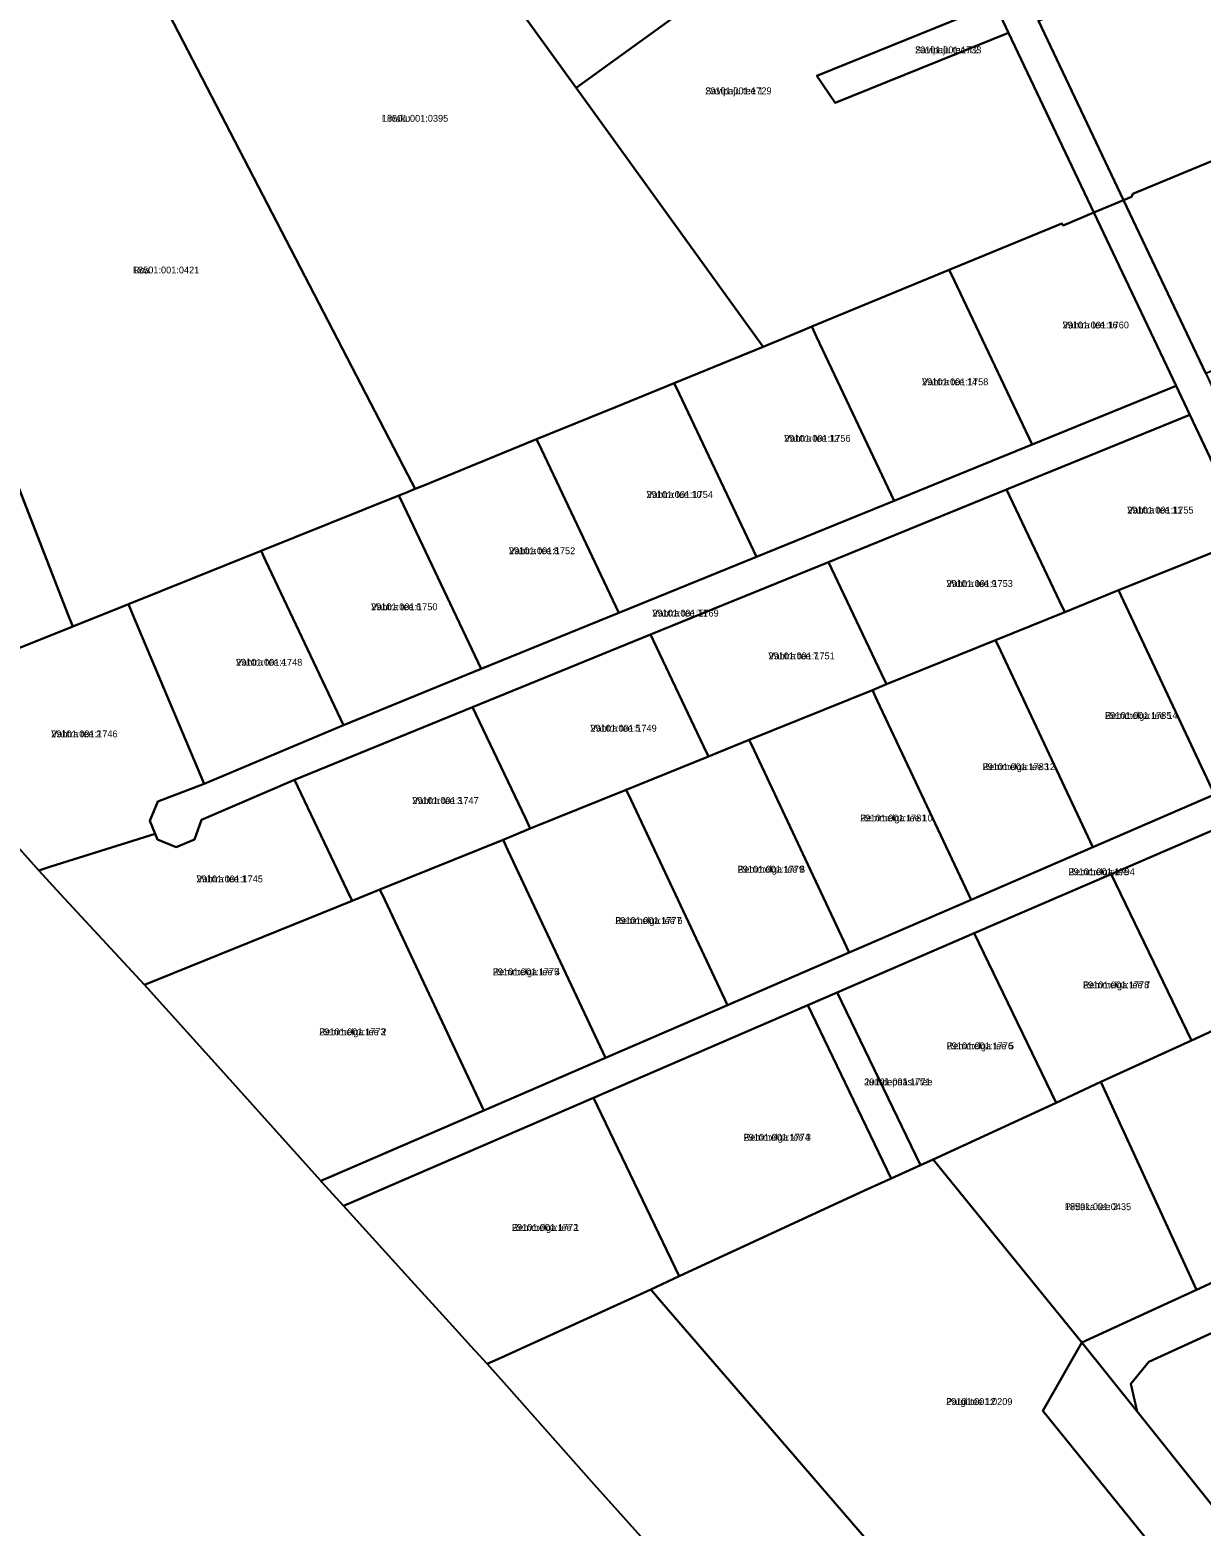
# Model space of a CAD drawing. Extents: x 660838 to 697091, y 6455678 to 6479886.
# Drawn here: x 663266.4 to 663522.4, y 6468685 to 6469012.3 of the extents above; entities that cross this region are included whole.
import ezdxf

# ---------------------------------------------------------------- set-up
doc = ezdxf.new("R2010")
doc.units = 0
for name, color, linetype in [('L_AADRESS', 7, 'Continuous'), ('PIIR', 7, 'Continuous'), ('TUNNUS', 7, 'Continuous')]:
    doc.layers.add(name, color=color, linetype=linetype)

msp = doc.modelspace()

# ---------------------------------------------------------------- linework, layer by layer
at = {"layer": 'PIIR'}
for points in [[(663486.87, 6469014.31), (663713.62, 6469105.91), (663720.33, 6469067.06), (663720.66, 6469065.11), (663650.19, 6469035.8), (663618.39, 6469022.56), (663590.11, 6469010.8), (663561.82, 6468999.03), (663533.52, 6468987.26), (663507.5, 6468976.43), (663507.24, 6468975.83), (663505.45, 6468975.08)], [(663350.61, 6468911.9), (663348.99, 6468915.02), (663260, 6469086.77), (663311.33, 6469099.39), (663313.4, 6469099.94), (663335.94, 6469068.7), (663352.57, 6469045.68), (663369.2, 6469022.66), (663385.83, 6468999.63), (663424.54, 6468945.93), (663426.65, 6468943.01), (663407.24, 6468935.07), (663394.38, 6468929.81), (663377.15, 6468922.76), (663352.52, 6468912.68)], [(663316.9, 6468898.34), (663287.89, 6468886.67), (663275.72, 6468881.78), (663274.68, 6468884.47), (663227.17, 6469006.58), (663255.16, 6469074.94), (663260, 6469086.77), (663348.99, 6468915.02), (663350.61, 6468911.9), (663348.56, 6468911.08), (663347.03, 6468910.46)], [(663415.89, 6469035.75), (663460.53, 6469053.44), (663477.31, 6469018), (663438.44, 6469002.3), (663442.46, 6468996.38), (663480.32, 6469011.67), (663498.96, 6468972.37), (663492.26, 6468969.54), (663491.95, 6468970), (663467.33, 6468959.83), (663437.31, 6468947.42), (663435.29, 6468946.59), (663426.65, 6468943.01), (663424.54, 6468945.93), (663385.83, 6468999.63), (663422.3, 6469026.09)], [(663460.53, 6469053.44), (663467.07, 6469056.05), (663483.87, 6469020.65), (663486.87, 6469014.31), (663505.45, 6468975.08), (663498.96, 6468972.37), (663480.32, 6469011.67), (663477.31, 6469018)], [(663406.04, 6469049.36), (663415.89, 6469035.75), (663422.3, 6469026.09), (663385.83, 6468999.63), (663369.2, 6469022.66)], [(663438.44, 6469002.3), (663477.31, 6469018), (663480.32, 6469011.67), (663442.46, 6468996.38)], [(663184.94, 6468925.36), (663214.15, 6468981.48), (663227.18, 6469006.66), (663274.68, 6468884.47), (663275.72, 6468881.78), (663234.78, 6468865.4), (663182.44, 6468922.95)], [(663507.5, 6468976.43), (663533.52, 6468987.26), (663534.59, 6468984.99), (663551.73, 6468948.87), (663523.45, 6468937.16), (663505.45, 6468975.08), (663507.24, 6468975.83)], [(663498.96, 6468972.37), (663505.45, 6468975.08), (663523.45, 6468937.16), (663526.45, 6468930.82), (663530.66, 6468921.94), (663539.34, 6468903.64), (663561.84, 6468856.19), (663554.36, 6468855.61), (663532.75, 6468901.15), (663519.97, 6468928.09), (663516.97, 6468934.43)], [(663492.26, 6468969.54), (663498.96, 6468972.37), (663516.97, 6468934.43), (663485.5, 6468921.6), (663468.41, 6468957.57), (663467.33, 6468959.83), (663491.95, 6468970)], [(663437.31, 6468947.42), (663467.33, 6468959.83), (663468.41, 6468957.57), (663485.5, 6468921.6), (663455.31, 6468909.3), (663438.38, 6468945.16)], [(663435.29, 6468946.59), (663437.31, 6468947.42), (663438.38, 6468945.16), (663455.31, 6468909.3), (663425.26, 6468897.06), (663408.31, 6468932.81), (663407.24, 6468935.07), (663426.65, 6468943.01)], [(663485.5, 6468921.6), (663516.97, 6468934.43), (663519.97, 6468928.09), (663479.86, 6468911.75), (663440.95, 6468895.89), (663402.03, 6468880.03), (663363.12, 6468864.18), (663324.23, 6468848.28), (663303.89, 6468839.52), (663302.38, 6468835.2), (663298.31, 6468833.53), (663294.25, 6468835.23), (663293.74, 6468836.47), (663292.58, 6468839.31), (663294.35, 6468843.53), (663304.43, 6468847.37), (663334.94, 6468860.25), (663365.04, 6468872.52), (663395.16, 6468884.79), (663425.26, 6468897.06), (663455.31, 6468909.3)], [(663394.38, 6468929.81), (663407.24, 6468935.07), (663408.31, 6468932.81), (663425.26, 6468897.06), (663395.16, 6468884.79), (663378.22, 6468920.5), (663377.15, 6468922.76)], [(663479.86, 6468911.75), (663519.97, 6468928.09), (663532.75, 6468901.15), (663520.04, 6468896.06), (663518.06, 6468895.26), (663504.39, 6468889.72), (663492.61, 6468884.94), (663491.54, 6468887.21)], [(663352.52, 6468912.68), (663377.15, 6468922.76), (663378.22, 6468920.5), (663395.16, 6468884.79), (663365.04, 6468872.52), (663348.11, 6468908.2), (663347.03, 6468910.46), (663348.56, 6468911.08), (663350.61, 6468911.9)], [(663316.9, 6468898.34), (663347.03, 6468910.46), (663348.11, 6468908.2), (663365.04, 6468872.52), (663334.94, 6468860.25), (663317.97, 6468896.08)], [(663440.95, 6468895.89), (663479.86, 6468911.75), (663491.54, 6468887.21), (663492.61, 6468884.94), (663477.48, 6468878.81), (663453.67, 6468869.16), (663452.59, 6468871.42)], [(663520.04, 6468896.06), (663532.75, 6468901.15), (663554.36, 6468855.61), (663548.83, 6468855.19), (663525.39, 6468845.05), (663505.46, 6468887.45), (663504.39, 6468889.72), (663518.06, 6468895.26)], [(663287.89, 6468886.67), (663316.9, 6468898.34), (663317.97, 6468896.08), (663334.94, 6468860.25), (663304.43, 6468847.37), (663288.86, 6468884.37)], [(663402.03, 6468880.03), (663440.95, 6468895.89), (663452.59, 6468871.42), (663453.67, 6468869.16), (663450.56, 6468867.9), (663423.65, 6468856.99), (663416.81, 6468854.22), (663414.72, 6468853.37), (663413.64, 6468855.63)], [(663492.61, 6468884.94), (663504.39, 6468889.72), (663505.46, 6468887.45), (663525.39, 6468845.05), (663498.76, 6468833.53), (663478.54, 6468876.54), (663477.48, 6468878.81)], [(663275.72, 6468881.78), (663287.89, 6468886.67), (663288.86, 6468884.37), (663304.43, 6468847.37), (663294.35, 6468843.53), (663292.58, 6468839.31), (663293.74, 6468836.47), (663270.95, 6468829.29), (663268.32, 6468828.46), (663263.54, 6468833.75), (663252.18, 6468846.23), (663239.84, 6468859.83), (663234.78, 6468865.4)], [(663363.12, 6468864.18), (663402.03, 6468880.03), (663413.64, 6468855.63), (663414.72, 6468853.37), (663396.73, 6468846.08), (663375.77, 6468837.59), (663374.7, 6468839.85)], [(663453.67, 6468869.16), (663477.48, 6468878.81), (663478.54, 6468876.54), (663498.76, 6468833.53), (663472.13, 6468822.01), (663451.63, 6468865.64), (663450.56, 6468867.9)], [(663423.65, 6468856.99), (663450.56, 6468867.9), (663451.63, 6468865.64), (663472.13, 6468822.01), (663445.5, 6468810.49), (663424.71, 6468854.73)], [(663324.23, 6468848.28), (663363.12, 6468864.18), (663374.7, 6468839.85), (663375.77, 6468837.59), (663369.82, 6468835.17), (663342.9, 6468824.26), (663336.83, 6468821.8), (663335.75, 6468824.06)], [(663416.81, 6468854.22), (663423.65, 6468856.99), (663424.71, 6468854.73), (663445.5, 6468810.49), (663418.87, 6468798.98), (663397.8, 6468843.82), (663396.73, 6468846.08), (663414.72, 6468853.37)], [(663303.89, 6468839.52), (663324.23, 6468848.28), (663335.75, 6468824.06), (663336.83, 6468821.8), (663291.41, 6468803.39), (663272.97, 6468823.32), (663268.32, 6468828.46), (663270.95, 6468829.29), (663293.74, 6468836.47), (663294.25, 6468835.23), (663298.31, 6468833.53), (663302.38, 6468835.2)], [(663375.77, 6468837.59), (663396.73, 6468846.08), (663397.8, 6468843.82), (663418.87, 6468798.98), (663392.24, 6468787.46), (663370.88, 6468832.91), (663369.82, 6468835.17)], [(663502.79, 6468827.65), (663533.31, 6468840.85), (663551.4, 6468805.53), (663531.41, 6468796.35), (663520.34, 6468791.26)], [(663342.9, 6468824.26), (663369.82, 6468835.17), (663370.88, 6468832.91), (663392.24, 6468787.46), (663365.61, 6468775.94), (663343.96, 6468822)], [(663472.84, 6468814.7), (663502.79, 6468827.65), (663520.34, 6468791.26), (663500.5, 6468782.17), (663490.73, 6468777.63)], [(663336.83, 6468821.8), (663342.9, 6468824.26), (663343.96, 6468822), (663365.61, 6468775.94), (663332.39, 6468761.57), (663329.97, 6468760.52), (663327.9, 6468762.8), (663309.41, 6468783.45), (663291.41, 6468803.39)], [(663442.89, 6468801.75), (663472.84, 6468814.7), (663490.73, 6468777.63), (663463.88, 6468765.21), (663461.09, 6468763.98)], [(663496.35, 6468725.18), (663521.4, 6468736.72), (663552.29, 6468750.92), (663583.18, 6468765.12), (663614.08, 6468779.32), (663644.97, 6468793.52), (663680.43, 6468809.82), (663685.3, 6468801.05), (663639.74, 6468780.11), (663622.2, 6468772.05), (663601.1, 6468762.35), (663570.84, 6468748.44), (663540.58, 6468734.53), (663510.99, 6468720.93), (663507.1, 6468716.16), (663508.46, 6468710.09)], [(663436.46, 6468798.97), (663442.89, 6468801.75), (663461.09, 6468763.98), (663454.67, 6468761.08)], [(663389.61, 6468778.71), (663436.46, 6468798.97), (663454.67, 6468761.08), (663448.81, 6468758.44), (663408.34, 6468739.7)], [(663552.29, 6468750.92), (663521.4, 6468736.72), (663500.5, 6468782.17), (663520.34, 6468791.26), (663531.41, 6468796.35)], [(663463.88, 6468765.21), (663490.73, 6468777.63), (663500.5, 6468782.17), (663521.4, 6468736.72), (663496.35, 6468725.18)], [(663337.35, 6468756.11), (663389.61, 6468778.71), (663408.34, 6468739.7), (663402.11, 6468736.81), (663369.35, 6468721.82), (663366.31, 6468720.48), (663364.63, 6468722.33), (663362.83, 6468724.31), (663357.37, 6468730.33), (663350.45, 6468737.96), (663334.92, 6468755.06)], [(663408.34, 6468739.7), (663448.81, 6468758.44), (663454.67, 6468761.08), (663461.09, 6468763.98), (663463.88, 6468765.21), (663496.35, 6468725.18), (663487.82, 6468710.24), (663513.22, 6468678.87), (663522.16, 6468667.94), (663531.26, 6468653.34), (663485.75, 6468635.95), (663484.87, 6468639.19), (663476.64, 6468649.37), (663450.99, 6468680.08), (663428.63, 6468706.01), (663404.51, 6468733.9), (663402.11, 6468736.81)], [(663369.35, 6468721.82), (663402.11, 6468736.81), (663404.51, 6468733.9), (663428.63, 6468706.01), (663450.99, 6468680.08), (663476.64, 6468649.37), (663484.87, 6468639.19), (663485.75, 6468635.95), (663450.73, 6468635.46), (663443.84, 6468635.35), (663430.87, 6468649.68), (663410.76, 6468670.66), (663389.74, 6468694.15), (663370.59, 6468715.76), (663366.31, 6468720.48)], [(663540.58, 6468734.53), (663562.72, 6468686.37), (663536.85, 6468674.48), (663508.46, 6468710.09), (663507.1, 6468716.16), (663510.99, 6468720.93)]]:
    msp.add_lwpolyline(points, close=True, dxfattribs=at)
for points in [[(663533.31, 6468840.85), (663502.79, 6468827.65), (663472.84, 6468814.7), (663442.89, 6468801.75), (663436.46, 6468798.97), (663389.61, 6468778.71), (663337.35, 6468756.11), (663334.92, 6468755.06), (663330.22, 6468760.24), (663329.97, 6468760.52), (663332.39, 6468761.57), (663365.61, 6468775.94), (663392.24, 6468787.46), (663418.87, 6468798.98), (663445.5, 6468810.49), (663472.13, 6468822.01), (663498.76, 6468833.53), (663525.39, 6468845.05)], [(663263.54, 6468833.75), (663268.32, 6468828.46), (663272.97, 6468823.32), (663291.41, 6468803.39), (663309.41, 6468783.45), (663327.9, 6468762.8), (663329.97, 6468760.52), (663330.22, 6468760.24), (663334.92, 6468755.06), (663350.45, 6468737.96), (663357.37, 6468730.33), (663362.83, 6468724.31), (663364.63, 6468722.33), (663366.31, 6468720.48), (663370.59, 6468715.76), (663389.74, 6468694.15), (663410.76, 6468670.66)], [(663513.22, 6468678.87), (663487.82, 6468710.24), (663496.35, 6468725.18), (663508.46, 6468710.09), (663536.85, 6468674.48)]]:
    msp.add_lwpolyline(points, dxfattribs=at)

# ---------------------------------------------------------------- texts
at = {"layer": 'L_AADRESS'}
for s, p in [('Savipaju tee T2', (663459.89, 6469007.19)), ('Savipaju tee 1', (663414.02, 6468998.23)), ('Liivaku', (663343.32, 6468992.22)), ('Roa', (663288.89, 6468959.04)), ('Vahtra tee 16', (663492.15, 6468947.01)), ('Vahtra tee 14', (663461.41, 6468934.58)), ('Vahtra tee 12', (663431.28, 6468922.22)), ('Vahtra tee 10', (663401.2, 6468909.93)), ('Vahtra tee 11', (663506.28, 6468906.52)), ('Vahtra tee 8', (663371.09, 6468897.63)), ('Vahtra tee 9', (663466.77, 6468890.46)), ('Vahtra tee 6', (663340.97, 6468885.37)), ('Vahtra tee T1', (663402.45, 6468883.98)), ('Vahtra tee 4', (663311.41, 6468873.23)), ('Vahtra tee 7', (663427.83, 6468874.63)), ('Vahtra tee 5', (663388.9, 6468858.81)), ('Remmelga tee 14', (663501.43, 6468861.6)), ('Vahtra tee 2', (663271.02, 6468857.57)), ('Remmelga tee 12', (663474.66, 6468850.39)), ('Vahtra tee 3', (663349.98, 6468842.99)), ('Remmelga tee 10', (663447.89, 6468839.17)), ('Remmelga tee 8', (663421.11, 6468827.96)), ('Remmelga tee', (663493.44, 6468827.41)), ('Vahtra tee 1', (663302.8, 6468825.84)), ('Remmelga tee 6', (663394.34, 6468816.74)), ('Remmelga tee 4', (663367.57, 6468805.52)), ('Remmelga tee 7', (663496.59, 6468802.66)), ('Remmelga tee 2', (663329.61, 6468792.39)), ('Remmelga tee 5', (663466.81, 6468789.33)), ('Juurdepääsu tee', (663448.78, 6468781.44)), ('Remmelga tee 3', (663422.41, 6468769.33)), ('Pihlaka tee 2', (663492.64, 6468754.14)), ('Remmelga tee 1', (663371.74, 6468749.6)), ('Pargi tee 12', (663466.68, 6468711.52))]:
    msp.add_text(s, height=1.5, dxfattribs=at).set_placement(p)
at = {"layer": 'TUNNUS'}
for s, p in [('29101:001:1733', (663459.89, 6469007.19)), ('29101:001:1729', (663414.02, 6468998.23)), ('18501:001:0395', (663343.32, 6468992.22)), ('18501:001:0421', (663288.89, 6468959.04)), ('29101:001:1760', (663492.15, 6468947.01)), ('29101:001:1758', (663461.41, 6468934.58)), ('29101:001:1756', (663431.28, 6468922.22)), ('29101:001:1754', (663401.2, 6468909.93)), ('29101:001:1755', (663506.28, 6468906.52)), ('29101:001:1752', (663371.09, 6468897.63)), ('29101:001:1753', (663466.77, 6468890.46)), ('29101:001:1750', (663340.97, 6468885.37)), ('29101:001:1769', (663402.45, 6468883.98)), ('29101:001:1748', (663311.41, 6468873.23)), ('29101:001:1751', (663427.83, 6468874.63)), ('29101:001:1749', (663388.9, 6468858.81)), ('29101:001:1785', (663501.43, 6468861.6)), ('29101:001:1746', (663271.02, 6468857.57)), ('29101:001:1783', (663474.66, 6468850.39)), ('29101:001:1747', (663349.98, 6468842.99)), ('29101:001:1781', (663447.89, 6468839.17)), ('29101:001:1779', (663421.11, 6468827.96)), ('29101:001:1794', (663493.44, 6468827.41)), ('29101:001:1745', (663302.8, 6468825.84)), ('29101:001:1777', (663394.34, 6468816.74)), ('29101:001:1775', (663367.57, 6468805.52)), ('29101:001:1778', (663496.59, 6468802.66)), ('29101:001:1773', (663329.61, 6468792.39)), ('29101:001:1776', (663466.81, 6468789.33)), ('29101:001:1771', (663448.78, 6468781.44)), ('29101:001:1774', (663422.41, 6468769.33)), ('18501:001:0435', (663492.64, 6468754.14)), ('29101:001:1772', (663371.74, 6468749.6)), ('29101:001:0209', (663466.68, 6468711.52))]:
    msp.add_text(s, height=1.5, dxfattribs=at).set_placement(p)

doc.saveas('drawing.dxf')
